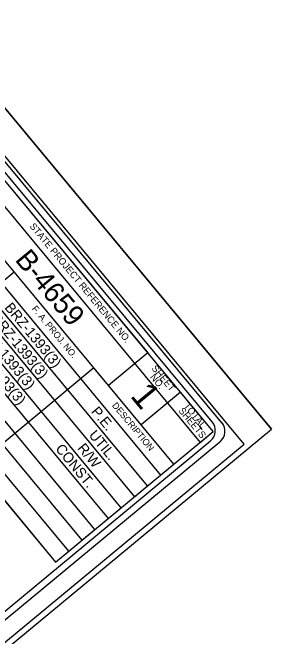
# Model space of a CAD drawing. Extents: x 2054826 to 2060231, y 685508 to 690809.
# Drawn here: x 2059947 to 2060231, y 688138 to 688824 of the extents above; entities that cross this region are included whole.
import ezdxf

# ---------------------------------------------------------------- set-up
doc = ezdxf.new("R2010")
doc.units = 0
for name, color, linetype in [('Sheet Cutting Line CELL', 7, 'Continuous'), ('Sheet Data Field CELL', 7, 'Continuous'), ('Sheet Plot Border Inside CELL', 7, 'Continuous'), ('Sheet Plot Border Outside CELL', 7, 'Continuous'), ('Sheet Title CELL', 7, 'Continuous')]:
    doc.layers.add(name, color=color, linetype=linetype)

msp = doc.modelspace()

# ---------------------------------------------------------------- linework, layer by layer
at = {"layer": 'Sheet Cutting Line CELL'}
msp.add_line((2058618.84, 690310.09), (2060231.25, 688365.67), dxfattribs=at)
at = {"layer": 'Sheet Plot Border Inside CELL'}
msp.add_lwpolyline([(2057387.09, 689263.34), (2058982.75, 687339.12), (2060201.02, 688349.37), (2058605.36, 690273.59)], close=True, dxfattribs=at)
at = {"layer": 'Sheet Plot Border Outside CELL'}
msp.add_lwpolyline([(2060231.25, 688365.67), (2058618.84, 690310.09), (2057348.74, 689256.87), (2058961.15, 687312.44)], close=True, dxfattribs=at)
at = {"layer": 'Sheet Title CELL'}
for points in [[(2060176.54, 688372.89), (2058759.45, 690081.81)], [(2060165.97, 688373.89), (2058806.35, 690013.48)], [(2059889.37, 688668.71), (2060152.68, 688351.18), (2060167.11, 688363.15), (2059903.79, 688680.66)], [(2059846.06, 688632.79), (2060109.37, 688315.26), (2060123.81, 688327.24), (2059860.5, 688644.77)], [(2059939.71, 688637.38), (2060095.3, 688449.72), (2060052, 688413.84), (2060036.01, 688433.12), (2059906.11, 688325.4), (2059993.92, 688219.52), (2060167.11, 688363.15), (2060131.21, 688406.45), (2060087.92, 688370.53)], [(2059817.19, 688608.85), (2060080.51, 688291.33), (2060094.93, 688303.29), (2059831.62, 688620.82)], [(2059788.34, 688584.93), (2060051.65, 688267.4), (2060066.08, 688279.37), (2059802.77, 688596.89)], [(2059818.34, 688431.22), (2059948.24, 688538.93), (2059896.39, 688601.46)], [(2059759.46, 688560.98), (2060022.77, 688243.45), (2060037.2, 688255.42), (2059773.9, 688572.93)], [(2059730.61, 688537.05), (2059993.92, 688219.52), (2060008.33, 688231.48), (2059745.04, 688549.02)], [(2058985.29, 687365.58), (2060174.56, 688351.79)], [(2059199.87, 687553.27), (2060164.01, 688352.78)]]:
    msp.add_lwpolyline(points, dxfattribs=at)
for centre in [(2060154.5, 688364.37), (2060165.06, 688363.38)]:
    msp.add_arc(centre, 15, 309.66721, 39.66721, dxfattribs=at)

# ---------------------------------------------------------------- texts
at = {"layer": 'Sheet Data Field CELL'}
for s, height, p in [('B-4659    ', 22.5, (2059948.36, 688551.96)), ('BRZ-1393(3)   ', 11.25, (2059937.18, 688499.29)), ('BRZ-1393(3)   ', 11.25, (2059922.74, 688487.32)), ('BRZ-1393(3)   ', 11.25, (2059908.32, 688475.36)), ('BRZ-1393(3)', 11.25, (2059898.07, 688458.36)), ('   P.E.   ', 11.25, (2060024.3, 688394.47)), ('UTIL.', 11.25, (2060029.74, 688358.9)), ('R/W', 11.25, (2060017.29, 688344.51)), ('CONST.', 11.25, (2059993.01, 688343.86))]:
    msp.add_text(s, height=height, rotation=309.66721, dxfattribs=at).set_placement(p)
at = {"layer": 'Sheet Title CELL'}
for s, height, p in [('STATE PROJECT REFERENCE NO.', 7.4997, (2059964.83, 688588.84)), ('F. A. PROJ. NO.', 7.2, (2059967.29, 688498.02)), ('SHEET', 7.5, (2060098.94, 688432.4)), ('NO.', 7.5, (2060097.21, 688422.88)), ('1', 29.02, (2060075.09, 688402.1)), ('DESCRIPTION', 7.2, (2060055.46, 688391.67)), ('TOTAL', 7.5, (2060134.02, 688390.95)), ('SHEETS', 7.5, (2060128.57, 688385.77))]:
    msp.add_text(s, height=height, rotation=309.66721, dxfattribs=at).set_placement(p)

doc.saveas('drawing.dxf')
